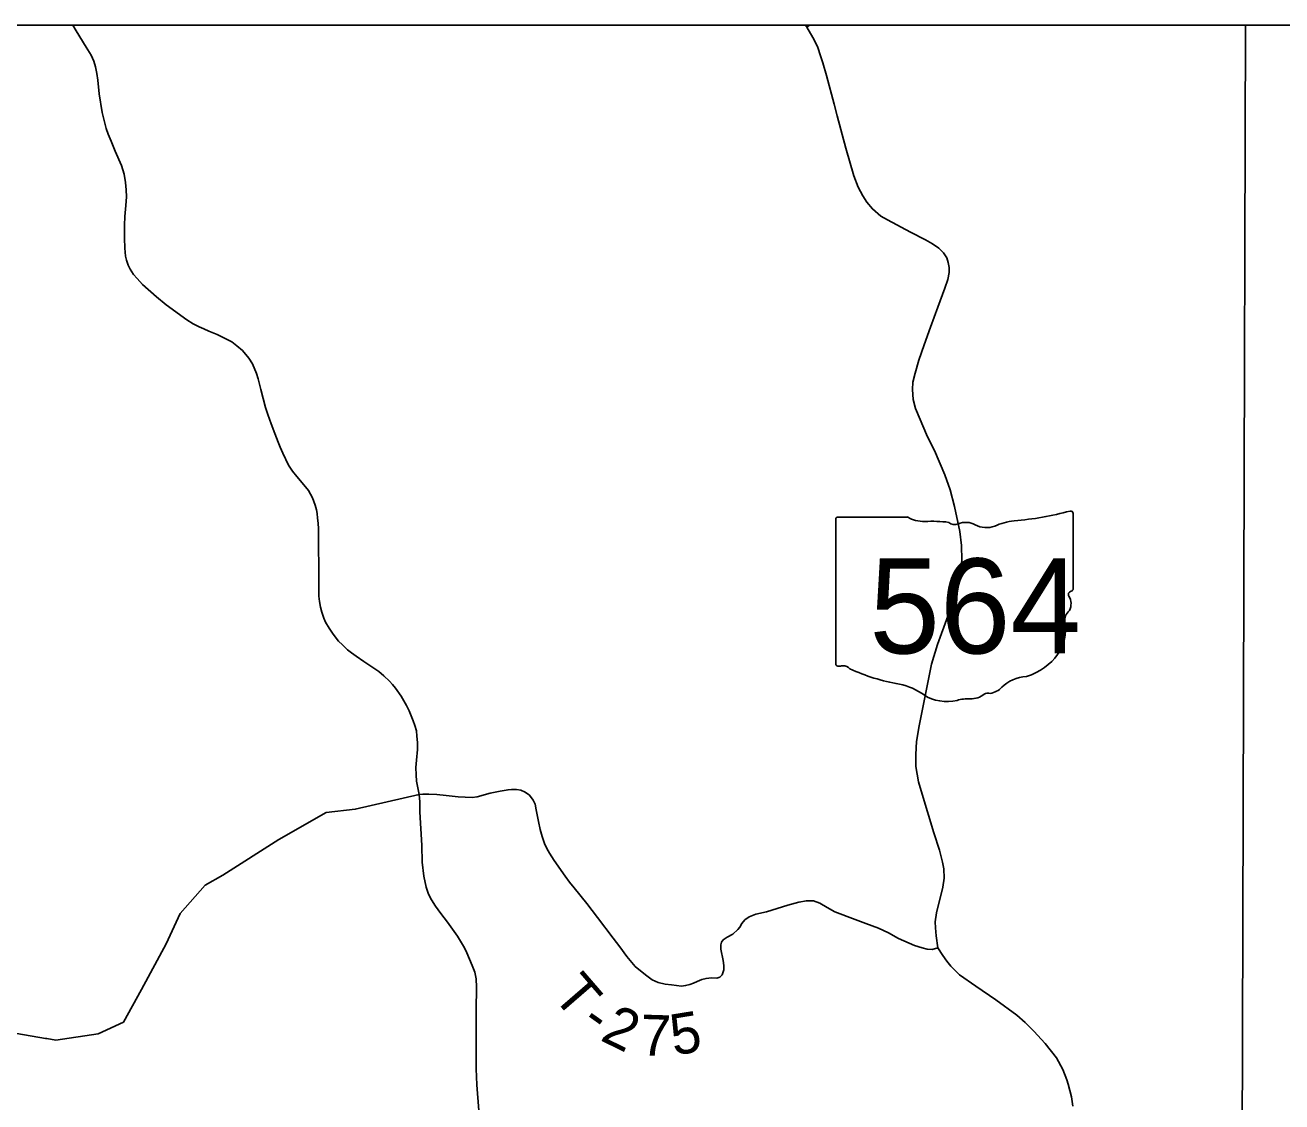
# Model space of a CAD drawing. Extents: x -10.5 to 40.6, y -3.2 to 22.
# Drawn here: x -7.857 to -6.111, y 19.405 to 20.9 of the extents above; entities that cross this region are included whole.
import ezdxf

# ---------------------------------------------------------------- set-up
doc = ezdxf.new("R2010")
doc.units = 0
for name, color, linetype in [('GM_X_County_Road', 7, 'Continuous'), ('GM_X_State_Location', 7, 'Continuous'), ('GM_X_State_Route', 7, 'Continuous'), ('GM_X_State_Shield', 7, 'Continuous'), ('GM_X_Township_Road', 7, 'Continuous'), ('GM_X_Township_Road_Text', 7, 'Continuous'), ('GM_X_Township_Text', 7, 'Continuous')]:
    doc.layers.add(name, color=color, linetype=linetype)

msp = doc.modelspace()

# ---------------------------------------------------------------- linework, layer by layer
at = {"layer": 'GM_X_County_Road'}
msp.add_line((-6.7712, 20.8971), (-6.7676, 20.9), dxfattribs=at)
at = {"layer": 'GM_X_State_Route'}
for points in [[(-6.7738, 20.9), (-6.7712, 20.8971), (-6.7627, 20.8829), (-6.7589, 20.8758), (-6.7558, 20.8689), (-6.7521, 20.8574), (-6.7488, 20.8476), (-6.7438, 20.83), (-6.7332, 20.7902), (-6.7289, 20.7741), (-6.7168, 20.7291), (-6.7056, 20.6907), (-6.6996, 20.6748), (-6.6932, 20.6628), (-6.6877, 20.654), (-6.6799, 20.6449), (-6.6681, 20.6346), (-6.6591, 20.6295), (-6.627, 20.6126), (-6.6061, 20.6017), (-6.5963, 20.5963), (-6.5877, 20.5903), (-6.5813, 20.5837), (-6.5767, 20.5768), (-6.5747, 20.5706), (-6.5733, 20.5636), (-6.5733, 20.5567), (-6.575, 20.5469), (-6.5792, 20.5348), (-6.5889, 20.5085), (-6.5991, 20.4808)], [(-6.5991, 20.4808), (-6.6082, 20.4562), (-6.6154, 20.4347), (-6.6207, 20.4167), (-6.6237, 20.4043), (-6.6245, 20.3942), (-6.6232, 20.3799), (-6.6203, 20.3676), (-6.6033, 20.3283), (-6.5939, 20.3092), (-6.5795, 20.2753), (-6.5721, 20.2545), (-6.566, 20.2316), (-6.5584, 20.1966), (-6.5561, 20.1774), (-6.5558, 20.1572), (-6.5583, 20.1352), (-6.5628, 20.1137), (-6.5896, 20.0398), (-6.5981, 20.0124), (-6.6151, 19.927), (-6.6187, 19.905), (-6.6197, 19.8872), (-6.6195, 19.8706), (-6.6158, 19.8492), (-6.6109, 19.8319), (-6.5946, 19.7784), (-6.587, 19.7542), (-6.5828, 19.7376), (-6.5808, 19.7282), (-6.5803, 19.7154), (-6.5821, 19.7029), (-6.5911, 19.6673), (-6.5929, 19.6548), (-6.5925, 19.6466), (-6.5916, 19.6352), (-6.5892, 19.6188), (-6.5824, 19.6082), (-6.5766, 19.6), (-6.5712, 19.593), (-6.5648, 19.5867), (-6.5589, 19.5812), (-6.5364, 19.5653), (-6.5085, 19.5466), (-6.4792, 19.5253), (-6.4676, 19.5151), (-6.4558, 19.503), (-6.4399, 19.4858), (-6.4242, 19.466), (-6.4153, 19.4497), (-6.4101, 19.4352)], [(-6.4101, 19.4352), (-6.408, 19.4294), (-6.4035, 19.4118), (-6.4014, 19.3986)]]:
    msp.add_lwpolyline(points, dxfattribs=at)
at = {"layer": 'GM_X_State_Shield'}
for p, q in [((-6.6311, 20.2169), (-6.7276, 20.2169)), ((-6.4013, 20.1172), (-6.4013, 20.2219)), ((-6.7309, 20.2135), (-6.7309, 20.0134)), ((-6.4013, 20.1172), (-6.4013, 20.1172))]:
    msp.add_line(p, q, dxfattribs=at)
for centre, major_axis, start_param, end_param in [((-6.7271, 20.2139), (0.00382, 0), 1.712693, 3.28349), ((-6.6081, 20.2402), (0.037, 0), 4.042523, 4.731795), ((-6.5187, 20.4898), (0.3495, 0), 4.814394, 5.042369), ((-6.4049, 20.2223), (0.00367, 0), 6.141152, 7.989035), ((-6.5958, 20.1046), (0.133, 0), 1.404758, 1.657858), ((-6.5656, 20.2149), (0.0107, 0), 3.836095, 5.185415), ((-6.55, 20.1918), (0.0222, 0), 0.950623, 2.079405), ((-6.5213, 20.2235), (0.0267, 0), 4.081561, 5.145723), ((-6.4741, 20.1558), (0.0703, 0), 1.699011, 2.107814), ((-6.4021, 20.1095), (0.00568, 0), 1.883978, 3.671073), ((-6.4052, 20.1168), (0.00393, 0), 5.05454, 6.418171), ((-6.4382, 20.0963), (0.0341, 0), 5.934695, 6.695948), ((-6.3881, 20.0734), (0.0248, 0), 2.387724, 3.262537), ((-6.4991, 20.0601), (0.0874, 0), 5.101752, 6.440018), ((-6.7271, 20.0129), (0.00385, 0), 3.00124, 4.508301), ((-6.7265, 20.0334), (0.0294, 0), 4.665946, 4.897461), ((-6.7205, 20.0018), (0.0106, 0), 0.519207, 1.627899), ((-6.5866, 20.1816), (0.2524, 0), 4.195997, 4.488961), ((-6.4622, 19.9572), (0.0479, 0), 1.647645, 2.488434), ((-6.6619, 19.9235), (0.079, 0), 0.823519, 1.323587), ((-6.5438, 19.9858), (0.0267, 0), 4.691044, 5.507374), ((-6.5197, 19.9665), (0.00752, 0), 1.147584, 2.315152), ((-6.5229, 19.994), (0.0282, 0), 4.937069, 5.64225), ((-6.5765, 20.0008), (0.0501, 0), 4.026481, 4.996735), ((-6.5475, 19.9316), (0.0412, 0), 1.495662, 1.94098)]:
    msp.add_ellipse(centre, major_axis=major_axis, ratio=0.8, start_param=start_param, end_param=end_param, dxfattribs=at)
at = {"layer": 'GM_X_Township_Road'}
for points in [[(-7.2268, 19.3926), (-7.2296, 19.4286), (-7.2303, 19.4507), (-7.2306, 19.4882), (-7.2306, 19.5125), (-7.2304, 19.5321), (-7.2297, 19.564), (-7.2305, 19.5758), (-7.2323, 19.5849), (-7.2358, 19.5941), (-7.2432, 19.6116), (-7.2467, 19.6188), (-7.2562, 19.635), (-7.2702, 19.6545), (-7.2793, 19.6663), (-7.2871, 19.6765), (-7.2925, 19.6855), (-7.2966, 19.6934), (-7.2999, 19.7027), (-7.3032, 19.7182), (-7.3053, 19.7377), (-7.306, 19.7608), (-7.3087, 19.8074), (-7.3088, 19.8213), (-7.3094, 19.8316), (-7.3104, 19.8362), (-7.312, 19.8432), (-7.3131, 19.8499), (-7.3139, 19.8587), (-7.314, 19.8692), (-7.3132, 19.8795), (-7.312, 19.8939), (-7.312, 19.9037), (-7.3126, 19.9128), (-7.3135, 19.9198), (-7.3154, 19.9273), (-7.3179, 19.9338), (-7.3234, 19.9476), (-7.3272, 19.9553), (-7.3345, 19.9682), (-7.3426, 19.9793), (-7.3464, 19.9843), (-7.351, 19.9891), (-7.3588, 19.9964), (-7.3658, 20.0023), (-7.3863, 20.0163), (-7.3972, 20.0236), (-7.4037, 20.0285), (-7.4089, 20.0327), (-7.4161, 20.0395), (-7.4214, 20.0447), (-7.4288, 20.0543), (-7.4344, 20.0625), (-7.4395, 20.071), (-7.4421, 20.0767), (-7.4447, 20.0848), (-7.4465, 20.0918), (-7.4479, 20.0997), (-7.449, 20.107), (-7.449, 20.123), (-7.4488, 20.1407), (-7.4492, 20.1826), (-7.4493, 20.1911), (-7.4496, 20.2003), (-7.45, 20.2086), (-7.4508, 20.2155), (-7.4514, 20.2218), (-7.4524, 20.2268), (-7.454, 20.2334), (-7.4578, 20.2437), (-7.4634, 20.2538), (-7.4721, 20.2643), (-7.4796, 20.273), (-7.4856, 20.2808), (-7.4912, 20.289), (-7.4989, 20.3054), (-7.5025, 20.3139), (-7.5053, 20.3207), (-7.5101, 20.3331), (-7.5151, 20.3464), (-7.5198, 20.3591), (-7.5232, 20.3691), (-7.5294, 20.3938), (-7.5316, 20.4035), (-7.5332, 20.409), (-7.5356, 20.4164), (-7.5412, 20.4296), (-7.546, 20.4373), (-7.5551, 20.448), (-7.5627, 20.4548), (-7.5696, 20.46), (-7.59, 20.4704), (-7.6016, 20.4751), (-7.6089, 20.4781), (-7.6153, 20.481), (-7.6235, 20.4854), (-7.6324, 20.4909), (-7.6608, 20.5117), (-7.6743, 20.5228), (-7.6937, 20.5399), (-7.7012, 20.5482), (-7.7062, 20.5539), (-7.7108, 20.561), (-7.7138, 20.5668), (-7.7161, 20.5737), (-7.7173, 20.5793), (-7.7185, 20.5902), (-7.7187, 20.6041), (-7.7187, 20.6222), (-7.7184, 20.6342), (-7.7172, 20.6496), (-7.7162, 20.6618), (-7.7164, 20.6711), (-7.7173, 20.6816), (-7.7192, 20.6929), (-7.7229, 20.705), (-7.7317, 20.7252), (-7.7374, 20.7391), (-7.7416, 20.7486), (-7.7444, 20.7566), (-7.7497, 20.7788), (-7.7541, 20.8046), (-7.7561, 20.8238), (-7.7572, 20.8327), (-7.7591, 20.842), (-7.7615, 20.85), (-7.7653, 20.8583), (-7.772, 20.8692), (-7.7862, 20.8922), (-7.7907, 20.9)], [(-7.8285, 19.4929), (-7.8266, 19.4926), (-7.8143, 19.4905), (-7.7556, 19.4994), (-7.7204, 19.5156), (-7.6954, 19.5609), (-7.661, 19.6242), (-7.6416, 19.6665), (-7.6066, 19.7055), (-7.5824, 19.7194), (-7.5043, 19.769), (-7.4386, 19.8067), (-7.3984, 19.8112), (-7.3094, 19.8316)], [(-7.3094, 19.8316), (-7.3045, 19.8319), (-7.296, 19.8322), (-7.2848, 19.8315), (-7.2719, 19.8302), (-7.2556, 19.8284), (-7.2361, 19.8273), (-7.2289, 19.8285), (-7.2108, 19.8336), (-7.1971, 19.8362), (-7.1861, 19.8381), (-7.1811, 19.8387), (-7.1742, 19.8385), (-7.1685, 19.8374), (-7.1625, 19.8348), (-7.1565, 19.8309), (-7.151, 19.8237), (-7.1485, 19.8183), (-7.1469, 19.8104), (-7.1439, 19.794), (-7.1413, 19.783), (-7.1388, 19.7731), (-7.1355, 19.7636), (-7.1324, 19.7566), (-7.1286, 19.7501), (-7.1219, 19.7401), (-7.1067, 19.718), (-7.1008, 19.71), (-7.0944, 19.7018), (-7.0767, 19.6803), (-7.0617, 19.6608), (-7.0399, 19.6321), (-7.0309, 19.6201), (-7.0209, 19.6066), (-7.0096, 19.5928), (-6.995, 19.5811), (-6.9858, 19.5744), (-6.9775, 19.5703), (-6.968, 19.5684), (-6.9591, 19.5672), (-6.945, 19.5655), (-6.9395, 19.5662), (-6.9334, 19.5676), (-6.9286, 19.5697), (-6.9235, 19.572), (-6.9171, 19.5745), (-6.911, 19.5762), (-6.9033, 19.5769), (-6.8959, 19.5766), (-6.8918, 19.5781), (-6.8886, 19.5813), (-6.8865, 19.5882), (-6.8866, 19.5943), (-6.8873, 19.601), (-6.8907, 19.6169), (-6.8907, 19.623), (-6.8898, 19.6267), (-6.8875, 19.6296), (-6.8817, 19.6335), (-6.874, 19.6377), (-6.8671, 19.6439), (-6.8643, 19.6475), (-6.8613, 19.6526), (-6.8573, 19.6575), (-6.8513, 19.6616), (-6.8419, 19.6656), (-6.8269, 19.6685), (-6.7974, 19.6779), (-6.7821, 19.6821), (-6.7716, 19.6841), (-6.7617, 19.6839), (-6.7531, 19.6806), (-6.7427, 19.6746), (-6.7322, 19.6685), (-6.7041, 19.6582), (-6.6891, 19.6525), (-6.6717, 19.6462), (-6.6577, 19.6394), (-6.6436, 19.6317), (-6.6216, 19.6221), (-6.6108, 19.6187), (-6.6039, 19.6166), (-6.5972, 19.6164), (-6.5892, 19.6188)], [(-7.8682, 19.4996), (-7.8285, 19.4929)]]:
    msp.add_lwpolyline(points, dxfattribs=at)
at = {"layer": 'GM_X_Township_Text'}
for points in [[(-6.192, 17.3965), (-6.1792, 18.1778), (-6.179, 18.1863), (-6.1678, 18.8746), (-6.1678, 18.8755), (-6.1618, 20.9), (-10.5445, 20.9), (-10.5445, 19.4241)], [(-3.7445, 16.8499), (-3.7445, 20.9), (-6.1618, 20.9)]]:
    msp.add_lwpolyline(points, dxfattribs=at)

# ---------------------------------------------------------------- texts
at = {"layer": 'GM_X_State_Location'}
for s in ['s', 'r']:
    msp.add_text(s, height=0.000189, dxfattribs=at).set_placement((-6.5698, 20.1001))
msp.add_text('564', height=0.000189, rotation=0, dxfattribs=at).set_placement((-6.6366, 20.0863))
at = {"layer": 'GM_X_State_Shield'}
msp.add_text('564', height=0.13184, dxfattribs=at).set_placement((-6.6843, 20.0275))
at = {"layer": 'GM_X_Township_Road_Text'}
for s, rotation, p in [('T', 310.8356, (-7.126, 19.5518)), ('2', 333.9358, (-7.0596, 19.491)), ('-', 324.5106, (-7.0873, 19.5097)), ('7', 358.2298, (-7.0028, 19.4693)), ('5', 9.1576, (-6.9561, 19.469))]:
    msp.add_text(s, height=0.0568, rotation=rotation, dxfattribs=at).set_placement(p)

doc.saveas('drawing.dxf')
